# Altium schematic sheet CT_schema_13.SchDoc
size 388 x 385 mm
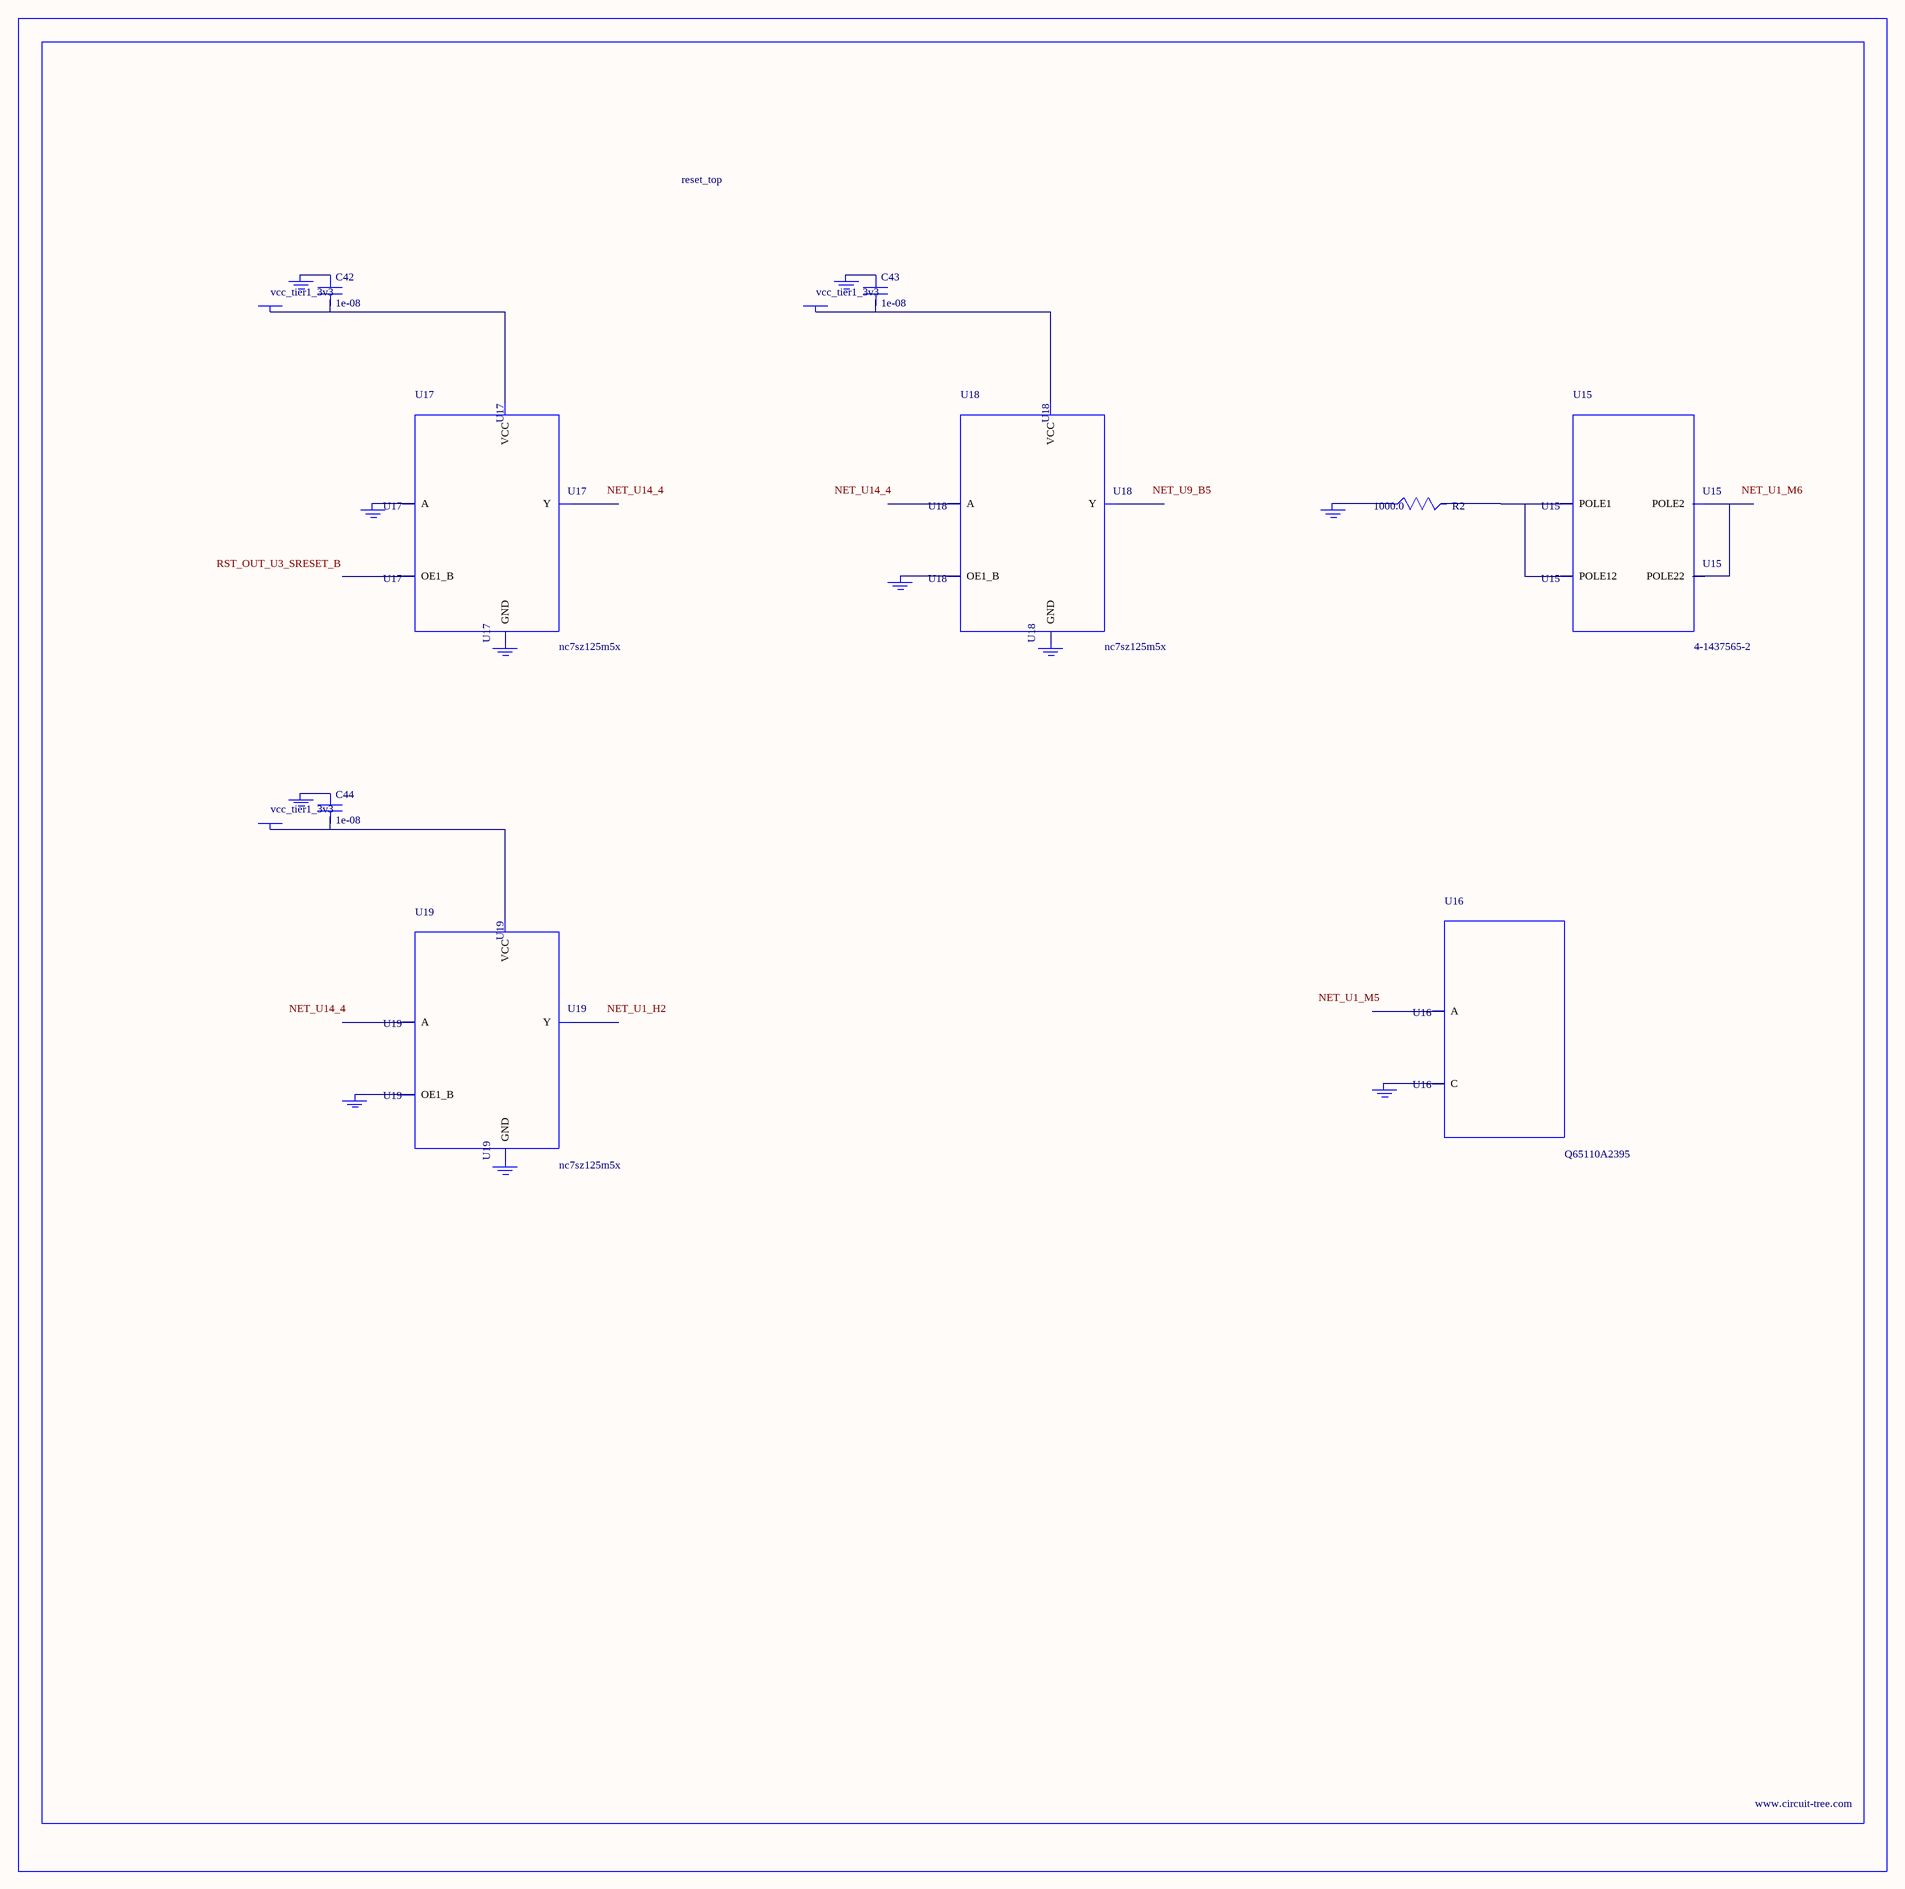
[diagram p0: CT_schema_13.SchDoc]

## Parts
BORDER12  (no value)
C42  1e-08  [C0402]
C43  1e-08  [C0402]
C44  1e-08  [C0402]
GND_INSTANCE_12_0  (no value)
GND_INSTANCE_12_1  (no value)
GND_INSTANCE_12_2  (no value)
GND_INSTANCE_12_3  (no value)
GND_INSTANCE_12_4  (no value)
GND_INSTANCE_12_5  (no value)
GND_INSTANCE_12_6  (no value)
GND_INSTANCE_12_7  (no value)
GND_INSTANCE_12_8  (no value)
GND_INSTANCE_12_9  (no value)
GND_INSTANCE_12_10  (no value)
POWER_INSTANCE_12_0  vcc_tier1_3v3
POWER_INSTANCE_12_1  vcc_tier1_3v3
POWER_INSTANCE_12_2  vcc_tier1_3v3
R2  1000.0  [R0603]
U15  4-1437565-2  [SW_4-1437565-2]
U16  Q65110A2395  [LGM67K-G1J2-24-Z]
U17  nc7sz125m5x  [NC7SZ125M5X]
U18  nc7sz125m5x  [NC7SZ125M5X]
U19  nc7sz125m5x  [NC7SZ125M5X]

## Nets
NetC42_1: C42.1 GND_INSTANCE_12_2.0(GND)
NetC42_2: C42.2 POWER_INSTANCE_12_0.0(PWR) U17.5(VCC)
NetC43_1: C43.1 GND_INSTANCE_12_5.0(GND)
NetC43_2: C43.2 POWER_INSTANCE_12_1.0(PWR) U18.5(VCC)
NetC44_1: C44.1 GND_INSTANCE_12_8.0(GND)
NetC44_2: C44.2 POWER_INSTANCE_12_2.0(PWR) U19.5(VCC)
NetGND_INSTANCE_12_0_0: GND_INSTANCE_12_0.0(GND) R2.1
NetGND_INSTANCE_12_1_0: GND_INSTANCE_12_1.0(GND) U16.C
NetGND_INSTANCE_12_3_0: GND_INSTANCE_12_3.0(GND) U17.2(A)
NetGND_INSTANCE_12_4_0: GND_INSTANCE_12_4.0(GND) U17.3(GND)
NetGND_INSTANCE_12_6_0: GND_INSTANCE_12_6.0(GND) U18.1(OE1_B)
NetGND_INSTANCE_12_7_0: GND_INSTANCE_12_7.0(GND) U18.3(GND)
NetGND_INSTANCE_12_9_0: GND_INSTANCE_12_9.0(GND) U19.1(OE1_B)
NetGND_INSTANCE_12_10_0: GND_INSTANCE_12_10.0(GND) U19.3(GND)
NetR2_2: R2.2 U15.1(POLE1) U15.2(POLE12)
NetU15_3: U15.3(POLE2) U15.4(POLE22)

Not connected (* = marked no-connect by the designer): U16 A; U17 1(OE1_B) 4(Y); U18 2(A) 4(Y); U19 2(A) 4(Y)

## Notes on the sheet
- Labels drawn without touching a wire or pin: NET_U1_H2, NET_U1_M5, NET_U1_M6, NET_U9_B5, NET_U14_4, RST_OUT_U3_SRESET_B

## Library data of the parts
BORDER12 = BORDER_PAGE12
C42-C44 = C0402C103K3RAC
GND_INSTANCE_12_0-GND_INSTANCE_12_10 = GND
POWER_INSTANCE_12_0-POWER_INSTANCE_12_2 = PWR
R2 = RC0603JR-071KL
